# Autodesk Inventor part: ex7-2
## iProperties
Author: Administrator
Created: 2001-03
Part Number: ex7-2
Document SubType Name: Modeling
Designer: Administrator
Control State: 0
Master: False
Checked Out: False
PropertySet Name: Design Tracking Control
Shininess: 20.0
PropertySet Name: _Private Model Information
Density: 0.0
Volumn: 0.0
Area: 0.0
PropertySet Name: Model Information
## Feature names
1. Extrusion1
2. Hole1
3. Hole2
4. Fillet1
